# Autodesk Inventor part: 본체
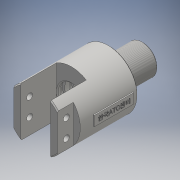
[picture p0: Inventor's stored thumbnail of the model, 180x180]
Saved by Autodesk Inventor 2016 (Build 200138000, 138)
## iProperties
Created: 2019-02
Part Number: 본체
Material: 일반
Document SubType Name: Modeling
Designer: USER
Density: 1 g/cm^3
Appearance: 기본값
Author: USER
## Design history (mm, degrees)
sketch "스케치1"
  geometry: C1 r 29 at (0, 0); 1 further point
  constraints: 1 centre point, 1 coincident
  dimensions: "d0" = 58 diameter of C1
extrude "돌출1" new body sketch "스케치1" distance "d1" = 74; taper "d2" = 0 deg
sketch "스케치2"
  geometry: C1 r 29 at (0, 0) reference; C2 r 13 at (0, 0); 1 further point
  constraints: 1 centre point, 1 coincident
  dimensions: "d3" = 26 diameter of C2
extrude "돌출2" join sketch "스케치2" distance "d4" = 5; taper "d5" = 0 deg
sketch "스케치3"
  geometry: C1 r 13 at (0, 0) reference; C2 r 15 at (0, 0); 1 further point
  constraints: 1 centre point, 1 coincident
  dimensions: "d6" = 30 diameter of C2
extrude "돌출3" join sketch "스케치3" distance "d7" = 29; taper "d8" = 0 deg
node "작업 평면1"
sketch "스케치4"
  geometry: L1 (0, 0)-(0, 36); L2 (-15, 0)-(-15, 36); L3 (15, 0)-(15, 36); L4 (-15, 36)-(15, 36); L5 (-15, 0)-(15, 0); L6 (-29, 0)-(29, 0) reference; L7 (29, 74)-(-29, 74) reference; L8 (-29, 0)-(29, 0) reference; L9 (-29, 0)-(-29, 74) reference
  constraints: 10 end point, 2 parallel, 1 collinear, 1 horizontal, 1 vertical
  dimensions: "d10" = 36 distance of L1.start L1.end; "d11" = 15 distance between parallel lines of L1 L2; "d12" = 15 distance between parallel lines of L1 L3; "d13" = 36 distance between parallel lines of L5 L4; "d14" = 38 distance between parallel lines of L7 L4
extrude "돌출4" cut sketch "스케치4" stored distance "d15" = 80; taper "d16" = 0 deg
sketch "스케치5"
  geometry: L1 (0, 0)-(0, 16); L2 (-22, 0)-(-22, 16); L3 (22, 0)-(22, 16); L4 (-22, 16)-(-29, 16); L5 (-29, 0)-(-29, 74) reference; L6 (-29, 0)-(-15, 0) reference; L7 (-22, 0)-(-29, 0); L8 (-29, 0)-(-29, 16); L9 (15, 0)-(29, 0) reference; L10 (22, 0)-(29, 0); L11 (22, 16)-(29, 16); L12 (29, 16)-(29, 0)
  constraints: 18 end point, 3 horizontal, 2 collinear, 2 parallel, 1 perpendicular, 1 point on line, 1 vertical
  dimensions: "d17" = 16 distance of L1.start L1.end; "d18" = 22 distance between parallel lines of L1 L2; "d19" = 22 distance between parallel lines of L1 L3; "d20" = 16 distance between parallel lines of L6 L4; "d21" = 16 distance between parallel lines of L9 L11
extrude "돌출5" cut sketch "스케치5" stored distance "d22" = 80; taper "d23" = 0 deg
node "작업 평면2"
sketch "스케치6"
  geometry: L1 (108, -15)-(108, 15) reference; L2 (108, 0)-(36, 0); L3 (36, 24.819)-(36, -24.819) reference; L4 (108, 0)-(108, 7); L5 (36, 0)-(36, 14); L6 (108, 7)-(86, 7); L7 (108, 0)-(108, 4); L8 (86, 4)-(63, 4); L9 (86, 7)-(86, 4); L10 (63, 4)-(63, 16); L11 (63, 16)-(56, 16); L12 (56, 16)-(56, 14); L13 (56, 14)-(52.35, 14); L14 (52.35, 17)-(52.35, 14); L15 (47.65, 17)-(47.65, 14); L16 (52.35, 17)-(47.65, 17); L17 (36, 14)-(38.65, 14); L18 (43.35, 14)-(43.35, 17); L19 (38.65, 14)-(38.65, 17); L20 (43.35, 14)-(47.65, 14); L21 (38.65, 17)-(43.35, 17); L22 (36, 29)-(74, 29) reference; 1 further point
  constraints: 38 end point, 6 perpendicular, 4 point on line, 3 horizontal, 2 midpoint, 1 vertical
  dimensions: "d25" = 7 distance of L2.start L4.end; "d32" = 22 distance of L4.end L6.end; "d33" = 4 distance of L2.start L7.end; "d34" = 23 distance of L8.start L8.end; "d35" = 3 distance of L6.end L8.start; "d37" = 7 distance of L10.end L11.end; "d38" = 2 distance of L11.end L12.end; "d42" = 3 distance of L13.end L14.start; "d44" = 3 distance of L15.start L15.end; "d52" = 4.7 distance of L19.end L18.end; "d53" = 4.7 distance of L14.start L15.start; "d54" = 28 diameter of L17 L2; "d55" = 34 diameter of L21 L2; "d56" = 32 diameter of L11 L2; "d57" = 4.3 distance of L18.start L15.end; "d58" = 3 distance of L18.start L18.end; "d60" = 12 distance between parallel lines of L22 L16; "d61" = 2.65 distance between parallel lines of L19 L3; "d62" = 3.65 distance of L12.end L13.end
revolve "회전1" sketch "스케치6" stored, may be unused: angle "d63" = 90 deg
sketch "스케치7"
  geometry: L1 (0, 0)-(-37.789, 0) reference; L2 (-18.894, 0)-(-18.894, 16); L3 (0, 16)-(-37.789, 16) reference; C1 r 3 at (-9.894, 9); C2 r 3 at (-27.894, 9)
  constraints: 2 centre point, 2 end point, 1 midpoint
  dimensions: "d64" = 6 diameter of C1; "d65" = 6 diameter of C2; "d66" = 9 distance from line of L1 C1.centre; "d67" = 9 distance from line of L1 C2.centre; "d68" = 9 distance from line of L2 C1.centre; "d69" = 9 distance from line of L2 C2.centre
extrude "돌출6" cut sketch "스케치7" distance "d70" = 50; taper "d71" = 0 deg
chamfer "모따기1" distance "d72" = 1; stored, may be unused: second distance "d73" = 2, angle "d74" = 45 deg
chamfer "모따기2" distance "d75" = 1; stored, may be unused: second distance "d76" = 2, angle "d77" = 45 deg
chamfer "모따기3" distance "d78" = 1; stored, may be unused: second distance "d79" = 2, angle "d80" = 45 deg
chamfer "모따기4" distance "d81" = 1; stored, may be unused: second distance "d82" = 2, angle "d83" = 45 deg
fillet "모깎기1" dims "d84" = 3
chamfer "모따기5" distance "d85" = 1; stored, may be unused: second distance "d86" = 2, angle "d87" = 45 deg
feature "스레드1" dims "d88" = 29, "d89" = 0
fillet "모깎기2" dims "d90" = 0.8
fillet "모깎기3" dims "d91" = 0.8
node "작업 평면3"
fillet "모깎기4" dims "d97" = 0.8
sketch "스케치9"
  geometry: L1 (29, -5)-(69, -5); L2 (69, -5)-(69, 5); L3 (69, 5)-(29, 5); L4 (29, 5)-(29, -5); L5 (69, 0)-(29, 0); L6 (74, 28)-(74, -28) reference; 1 further point
  constraints: 10 end point, 2 midpoint, 2 parallel, 1 horizontal, 1 horizontal alignment, 1 perpendicular
  dimensions: "d104" = 10 distance of L3.end L1.start; "d105" = 40 distance of L2.end L3.end; "d106" = 5 distance between parallel lines of L6 L2
extrude "돌출7" join sketch "스케치9" distance "d107" = 1; taper "d108" = 0 deg
node "작업 평면4"
sketch "스케치10"
  geometry: L1 (69, 5)-(29, 5) reference; L2 (29, 5)-(29, -5) reference; 2 further points
  constraints: 1 other
  dimensions: "d110" = 5 distance from line of L1 point (49, 0); "d111" = 20 distance from line of L2 point (49, 0)
feature "엠보싱2" sketch "스케치10" dims "d10" = 36, "d11" = 15, "d12" = 15, "d13" = 36, "d14" = 38, "d112" = 0.5, "d113" = 0
chamfer "모따기9" distance "d120" = 1; stored, may be unused: second distance "d121" = 2, angle "d122" = 45 deg
feature "스레드2" dims "d123" = 18, "d124" = 0
node "솔리드1"
node "투영된 루프1"
node "투영된 루프2"
node "투영된 루프3"
other parameters: "d9" = 0, "d24" = 0, "d95" = 29
